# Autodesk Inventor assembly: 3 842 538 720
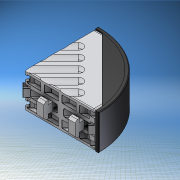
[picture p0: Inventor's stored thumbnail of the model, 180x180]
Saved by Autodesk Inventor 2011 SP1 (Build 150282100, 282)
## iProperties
Created: 2011-02
Part Number: 3 842 538 720
Document SubType Name: Assembly
Designer: SRW
Description: 45x90 GUSSET DESIGNLINE
Stock Number: 3 842 538 720
Author: SRW
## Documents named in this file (3)
- C:\_Work\Projects\Libraries\Purchased Parts\Bosch Rexroth\Structural Framing System\Profile Connectors\Gussets\45x90 Gusset\3 842 538 720 - 45x90 Gusset designLINE.iam
- C:\_Work\Projects\Libraries\Purchased Parts\Bosch Rexroth\Structural Framing System\Profile Connectors\Gussets\45x90 Gusset\3 842 523 570 - 45x90 Gusset with fasteners.ipt
- C:\_Work\Projects\Libraries\Purchased Parts\Bosch Rexroth\Structural Framing System\Profile Connectors\Gussets\45x90 Gusset\3 842 523 572 - 45x90 Round cover cap.ipt
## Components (2 placed, 2 different names)
1. 3 842 523 570 - 45x90 Gusset with fasteners:1 — Mate:1, Flush:1, Mate:2
2. 3 842 523 572 - 45x90 Round cover cap:1 — Mate:1, Flush:1, Mate:2
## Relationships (3: Mate 2, Flush 1)
- Mate:1: 3 842 523 570 - 45x90 Gusset with fasteners:1 ↔ 3 842 523 572 - 45x90 Round cover cap:1
- Flush:1: 3 842 523 570 - 45x90 Gusset with fasteners:1 ↔ 3 842 523 572 - 45x90 Round cover cap:1
- Mate:2: 3 842 523 570 - 45x90 Gusset with fasteners:1 ↔ 3 842 523 572 - 45x90 Round cover cap:1
